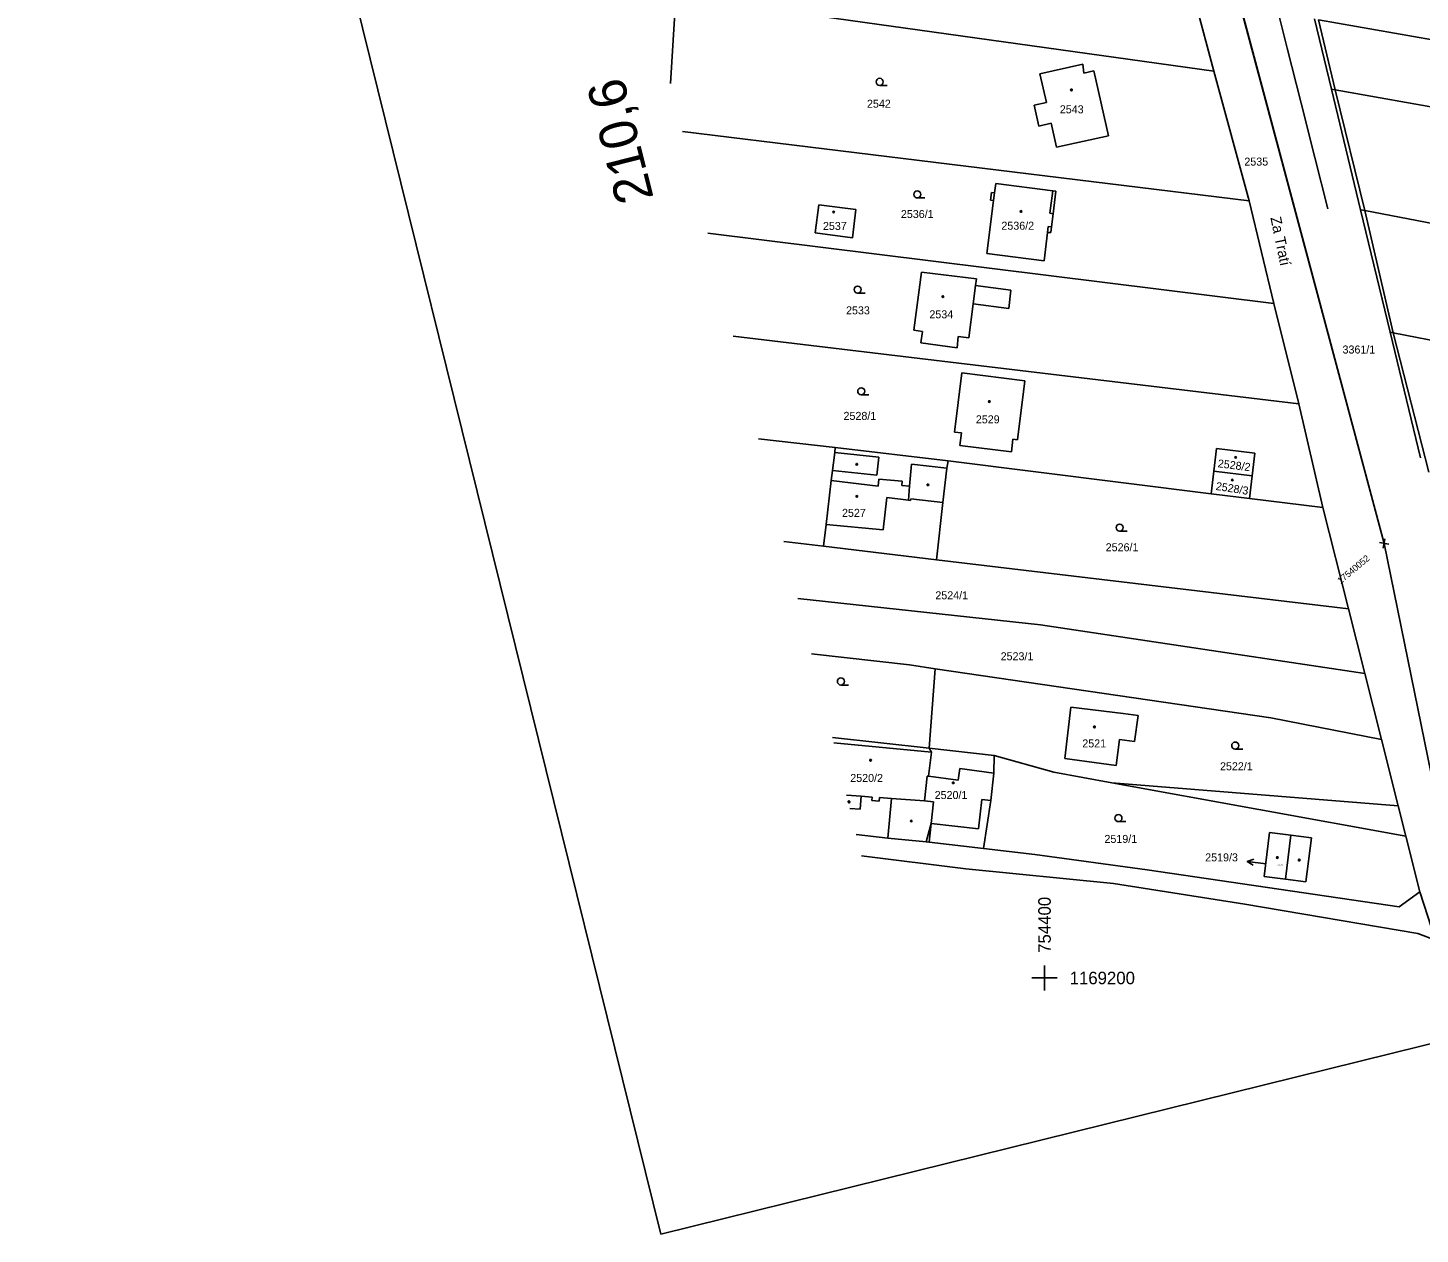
# Model space of a CAD drawing. Extents: x -754679 to -754173, y -1169241 to -1168288.
# Drawn here: x -754562 to -754340.2, y -1169240.8 to -1169048.7 of the extents above; entities that cross this region are included whole.
import ezdxf

# ---------------------------------------------------------------- set-up
doc = ezdxf.new("R2010")
doc.units = 0
for name, color, linetype in [('Default', 7, 'Continuous'), ('Vrstva 1', 7, 'Continuous'), ('Vrstva 13', 7, 'Continuous'), ('Vrstva 15', 7, 'Continuous'), ('Vrstva 16', 7, 'Continuous'), ('Vrstva 18', 7, 'Continuous'), ('Vrstva 19', 7, 'Continuous'), ('Vrstva 25', 7, 'Continuous'), ('Vrstva 4', 7, 'Continuous'), ('Vrstva 52', 7, 'Continuous'), ('Vrstva 53', 7, 'Continuous'), ('Vrstva 60', 7, 'Continuous'), ('Vrstva 61', 7, 'Continuous'), ('Vrstva 7', 7, 'Continuous')]:
    doc.layers.add(name, color=color, linetype=linetype)

msp = doc.modelspace()

# ---------------------------------------------------------------- linework, layer by layer
at = {"layer": 'Default'}
for points in [[(-754400, -1169202), (-754400, -1169200), (-754400, -1169198)], [(-754402, -1169200), (-754400, -1169200), (-754398, -1169200)]]:
    msp.add_lwpolyline(points, dxfattribs=at)
at = {"layer": 'Vrstva 1'}
for p, q in [((-754386.06, -1168980.52), (-754345.91, -1169130.8)), ((-754458.74, -1169043.6), (-754459.56, -1169057.52)), ((-754373.03, -1169055.57), (-754458.74, -1169043.6)), ((-754375.93, -1169044.62), (-754373.03, -1169055.57)), ((-754356.98, -1169047.27), (-754354.28, -1169058.43)), ((-754295.74, -1169058.05), (-754356.33, -1169047.39)), ((-754393.88, -1169054.46), (-754400.75, -1169056)), ((-754393.73, -1169055.89), (-754393.88, -1169054.46)), ((-754400.75, -1169056), (-754399.7, -1169060.55)), ((-754392.13, -1169055.53), (-754393.73, -1169055.89)), ((-754389.81, -1169065.88), (-754392.13, -1169055.53)), ((-754367.41, -1169076.22), (-754373.03, -1169055.57)), ((-754354.28, -1169058.43), (-754353.72, -1169058.53)), ((-754354.28, -1169058.43), (-754349.64, -1169077.64)), ((-754292.92, -1169069.45), (-754353.72, -1169058.53)), ((-754401.67, -1169061), (-754399.7, -1169060.55)), ((-754400.91, -1169064.33), (-754401.67, -1169061)), ((-754398.94, -1169063.88), (-754400.91, -1169064.33)), ((-754398.07, -1169067.71), (-754398.94, -1169063.88)), ((-754457.66, -1169065.21), (-754367.41, -1169076.22)), ((-754389.81, -1169065.88), (-754398.07, -1169067.71)), ((-754408.58, -1169076.1), (-754408.43, -1169074.92)), ((-754408.43, -1169074.92), (-754407.96, -1169074.98)), ((-754407.96, -1169074.98), (-754407.77, -1169073.49)), ((-754407.77, -1169073.49), (-754398.68, -1169074.63)), ((-754398.68, -1169074.63), (-754398.18, -1169074.69)), ((-754398.18, -1169074.69), (-754398.64, -1169078.28)), ((-754436.55, -1169081.34), (-754435.96, -1169076.87)), ((-754435.96, -1169076.87), (-754430.07, -1169077.61)), ((-754409.17, -1169084.63), (-754408.11, -1169076.16)), ((-754408.11, -1169076.16), (-754408.58, -1169076.1)), ((-754367.41, -1169076.22), (-754363.46, -1169092.56)), ((-754430.07, -1169077.61), (-754430.61, -1169082.11)), ((-754398.64, -1169078.28), (-754398.9, -1169080.39)), ((-754348.95, -1169077.77), (-754349.64, -1169077.64)), ((-754349.64, -1169077.64), (-754344.93, -1169097.16)), ((-754287.96, -1169089.49), (-754348.95, -1169077.77)), ((-754453.66, -1169081.38), (-754363.46, -1169092.56)), ((-754430.61, -1169082.11), (-754436.55, -1169081.34)), ((-754399.51, -1169081.26), (-754400.08, -1169085.77)), ((-754399.01, -1169081.3), (-754399.51, -1169081.26)), ((-754398.9, -1169080.39), (-754399.01, -1169081.3)), ((-754400.08, -1169085.77), (-754409.17, -1169084.63)), ((-754420.84, -1169096.85), (-754419.6, -1169087.58)), ((-754419.6, -1169087.58), (-754410.85, -1169088.67)), ((-754410.85, -1169088.67), (-754410.99, -1169089.74)), ((-754410.99, -1169089.74), (-754405.34, -1169090.46)), ((-754405.34, -1169090.46), (-754405.71, -1169093.36)), ((-754411.36, -1169092.64), (-754412.06, -1169098.06)), ((-754405.71, -1169093.36), (-754411.36, -1169092.64)), ((-754363.46, -1169092.56), (-754359.5, -1169108.58)), ((-754419.46, -1169097.03), (-754420.84, -1169096.85)), ((-754419.69, -1169098.86), (-754419.46, -1169097.03)), ((-754344.93, -1169097.16), (-754344.43, -1169097.26)), ((-754344.93, -1169097.16), (-754340.1, -1169117.15)), ((-754344.43, -1169097.26), (-754283.09, -1169109.21)), ((-754359.5, -1169108.58), (-754449.6, -1169097.79)), ((-754413.94, -1169099.63), (-754419.69, -1169098.86)), ((-754413.75, -1169097.84), (-754413.94, -1169099.63)), ((-754412.06, -1169098.06), (-754413.75, -1169097.84)), ((-754414.32, -1169113.06), (-754413.15, -1169103.64)), ((-754413.15, -1169103.64), (-754403.13, -1169104.88)), ((-754403.13, -1169104.88), (-754404.31, -1169114.28)), ((-754359.5, -1169108.58), (-754355.64, -1169125.06)), ((-754433.34, -1169115.54), (-754445.56, -1169114.14)), ((-754413.22, -1169113.2), (-754414.32, -1169113.06)), ((-754413.47, -1169115.21), (-754413.22, -1169113.2)), ((-754405.03, -1169114.19), (-754405.28, -1169116.22)), ((-754404.31, -1169114.28), (-754405.03, -1169114.19)), ((-754433.43, -1169116.33), (-754433.77, -1169119.16)), ((-754433.34, -1169115.54), (-754433.43, -1169116.33)), ((-754415.34, -1169117.65), (-754433.34, -1169115.54)), ((-754405.28, -1169116.22), (-754413.47, -1169115.21)), ((-754373.02, -1169119.29), (-754372.58, -1169115.67)), ((-754372.58, -1169115.67), (-754366.48, -1169116.4)), ((-754366.48, -1169116.4), (-754366.91, -1169120.03)), ((-754433.97, -1169120.78), (-754433.77, -1169119.16)), ((-754416.22, -1169124.26), (-754415.57, -1169118.79)), ((-754415.34, -1169117.65), (-754415.57, -1169118.79)), ((-754373.45, -1169122.92), (-754415.34, -1169117.65)), ((-754373.45, -1169122.92), (-754373.02, -1169119.29)), ((-754366.91, -1169120.03), (-754373.02, -1169119.29)), ((-754434.8, -1169127.79), (-754433.97, -1169120.78)), ((-754366.91, -1169120.03), (-754367.35, -1169123.65)), ((-754367.35, -1169123.65), (-754373.45, -1169122.92)), ((-754355.64, -1169125.06), (-754367.35, -1169123.65)), ((-754417.21, -1169133.39), (-754416.22, -1169124.26)), ((-754351.59, -1169141.22), (-754355.64, -1169125.06)), ((-754435.21, -1169131.25), (-754434.8, -1169127.79)), ((-754441.52, -1169130.5), (-754435.21, -1169131.25)), ((-754417.21, -1169133.39), (-754435.21, -1169131.25)), ((-754345.91, -1169130.8), (-754333.91, -1169189.61)), ((-754351.59, -1169141.22), (-754417.21, -1169133.39)), ((-754439.28, -1169139.55), (-754400.66, -1169143.78)), ((-754351.59, -1169141.22), (-754348.98, -1169151.49)), ((-754348.98, -1169151.49), (-754400.66, -1169143.78)), ((-754421.5, -1169150.11), (-754437.1, -1169148.37)), ((-754417.44, -1169150.77), (-754421.5, -1169150.11)), ((-754417.44, -1169150.77), (-754418.36, -1169163.42)), ((-754363.94, -1169158.55), (-754417.44, -1169150.77)), ((-754348.98, -1169151.49), (-754346.3, -1169162)), ((-754395.79, -1169156.85), (-754396.77, -1169165.07)), ((-754387.47, -1169157.88), (-754395.79, -1169156.85)), ((-754385.1, -1169158.21), (-754387.47, -1169157.88)), ((-754385.67, -1169162.35), (-754385.1, -1169158.21)), ((-754346.3, -1169162), (-754363.94, -1169158.55)), ((-754418.36, -1169163.42), (-754433.8, -1169161.68)), ((-754418.36, -1169163.42), (-754408.03, -1169164.58)), ((-754418.36, -1169163.42), (-754418.03, -1169164.01)), ((-754388.61, -1169166.17), (-754388.04, -1169162.02)), ((-754388.04, -1169162.02), (-754385.67, -1169162.35)), ((-754343.65, -1169172.58), (-754346.3, -1169162)), ((-754418.03, -1169164.01), (-754418.47, -1169167.87)), ((-754408.03, -1169164.58), (-754408.08, -1169167.38)), ((-754398.5, -1169167.22), (-754408.03, -1169164.58)), ((-754396.77, -1169165.07), (-754388.61, -1169166.17)), ((-754419.12, -1169171.81), (-754418.67, -1169167.85)), ((-754418.47, -1169167.87), (-754418.67, -1169167.85)), ((-754408.08, -1169167.38), (-754408.55, -1169171.72)), ((-754389.3, -1169168.9), (-754398.5, -1169167.22)), ((-754342.43, -1169177.43), (-754389.3, -1169168.9)), ((-754417.68, -1169171.97), (-754419.12, -1169171.81)), ((-754418.05, -1169175.38), (-754417.68, -1169171.97)), ((-754408.55, -1169171.72), (-754409.73, -1169179.38)), ((-754342.43, -1169177.43), (-754343.65, -1169172.58)), ((-754429.98, -1169177.14), (-754424.97, -1169177.74)), ((-754418.05, -1169175.38), (-754418.84, -1169178.34)), ((-754365.03, -1169183.83), (-754364.13, -1169176.81)), ((-754364.13, -1169176.81), (-754360.78, -1169177.24)), ((-754360.78, -1169177.24), (-754357.48, -1169177.66)), ((-754424.97, -1169177.74), (-754418.84, -1169178.34)), ((-754418.84, -1169178.34), (-754418.38, -1169178.38)), ((-754418.38, -1169178.38), (-754409.73, -1169179.38)), ((-754409.73, -1169179.38), (-754401.54, -1169180.32)), ((-754357.48, -1169177.66), (-754358.38, -1169184.68)), ((-754340.21, -1169186.28), (-754342.43, -1169177.43)), ((-754401.54, -1169180.32), (-754383.66, -1169182.78)), ((-754383.66, -1169182.78), (-754343.51, -1169188.69)), ((-754361.6, -1169184.27), (-754365.03, -1169183.83)), ((-754358.38, -1169184.68), (-754361.6, -1169184.27)), ((-754343.51, -1169188.69), (-754340.21, -1169186.28)), ((-754340.21, -1169186.28), (-754337.71, -1169193.96))]:
    msp.add_line(p, q, dxfattribs=at)
msp.add_lwpolyline([(-754354.86, -1169077.5), (-754356.93, -1169069.33), (-754359.12, -1169060.65), (-754361.33, -1169051.91), (-754363.43, -1169043.59), (-754365, -1169037.37), (-754367.34, -1169028.11), (-754369.54, -1169019.37), (-754371.76, -1169010.62)], dxfattribs=at)
at = {"layer": 'Vrstva 13'}
for p, q in [((-754429.14, -1169180.52), (-754412.56, -1169182.61)), ((-754412.56, -1169182.61), (-754389.02, -1169184.95)), ((-754389.02, -1169184.95), (-754368.1, -1169188.22)), ((-754368.1, -1169188.22), (-754340.53, -1169192.94)), ((-754340.53, -1169192.94), (-754337.71, -1169193.96))]:
    msp.add_line(p, q, dxfattribs=at)
at = {"layer": 'Vrstva 16'}
msp.add_line((-754367.69, -1169181.43), (-754364.71, -1169181.81), dxfattribs=at)
msp.add_lwpolyline([(-754366.76, -1169182.05), (-754367.69, -1169181.43), (-754366.63, -1169181.06)], dxfattribs=at)
at = {"layer": 'Vrstva 25'}
for p, q in [((-754426.26, -1169057.84), (-754425.06, -1169057.84)), ((-754420.27, -1169075.77), (-754419.07, -1169075.77)), ((-754429.77, -1169090.93), (-754428.57, -1169090.93)), ((-754429.2, -1169107.12), (-754428, -1169107.12)), ((-754388.03, -1169128.83), (-754386.83, -1169128.83)), ((-754432.44, -1169153.34), (-754431.24, -1169153.34)), ((-754369.62, -1169163.54), (-754368.42, -1169163.54)), ((-754431.3, -1169171.82), (-754431.22, -1169172.13)), ((-754388.22, -1169175.1), (-754387.02, -1169175.1))]:
    msp.add_line(p, q, dxfattribs=at)
for centre, radius in [((-754426.26, -1169057.28), 0.562), ((-754395.71, -1169058.56), 0.131), ((-754420.27, -1169075.21), 0.562), ((-754433.58, -1169078.01), 0.131), ((-754403.75, -1169077.92), 0.131), ((-754429.77, -1169090.37), 0.562), ((-754416.19, -1169091.48), 0.131), ((-754429.2, -1169106.56), 0.562), ((-754408.79, -1169108.2), 0.131), ((-754369.54, -1169117.08), 0.131), ((-754429.91, -1169118.19), 0.131), ((-754418.58, -1169121.46), 0.131), ((-754370.09, -1169120.69), 0.131), ((-754429.89, -1169123.3), 0.131), ((-754388.03, -1169128.27), 0.562), ((-754432.44, -1169152.78), 0.562), ((-754392.04, -1169160.01), 0.131), ((-754369.62, -1169162.98), 0.562), ((-754427.71, -1169165.32), 0.131), ((-754414.55, -1169168.92), 0.131), ((-754421.23, -1169174.99), 0.131), ((-754388.22, -1169174.54), 0.562), ((-754362.9, -1169180.82), 0.131), ((-754359.42, -1169181.23), 0.131)]:
    msp.add_circle(centre, radius, dxfattribs=at)
msp.add_arc((-754431.19, -1169171.96), 0.175, 260.291, 127.4882, dxfattribs=at)
at = {"layer": 'Vrstva 4'}
for p, q in [((-754353.72, -1169058.53), (-754356.33, -1169047.39)), ((-754348.95, -1169077.77), (-754353.72, -1169058.53)), ((-754408.11, -1169076.16), (-754407.96, -1169074.98)), ((-754399.13, -1169078.22), (-754398.68, -1169074.63)), ((-754398.64, -1169078.28), (-754399.13, -1169078.22)), ((-754344.43, -1169097.26), (-754348.95, -1169077.77)), ((-754399.51, -1169081.26), (-754399.4, -1169080.33)), ((-754399.4, -1169080.33), (-754398.9, -1169080.39)), ((-754410.99, -1169089.74), (-754411.36, -1169092.64)), ((-754338.76, -1169119.45), (-754344.43, -1169097.26)), ((-754433.43, -1169116.33), (-754426.37, -1169117.08)), ((-754426.37, -1169117.08), (-754426.71, -1169119.93)), ((-754426.71, -1169119.93), (-754433.77, -1169119.16)), ((-754421.21, -1169118.16), (-754421.49, -1169121.69)), ((-754415.57, -1169118.79), (-754421.21, -1169118.16)), ((-754426.5, -1169121.67), (-754433.97, -1169120.78)), ((-754426.37, -1169120.58), (-754426.5, -1169121.67)), ((-754422.67, -1169120.89), (-754426.37, -1169120.58)), ((-754422.73, -1169121.59), (-754422.67, -1169120.89)), ((-754421.49, -1169121.69), (-754422.73, -1169121.59)), ((-754421.67, -1169123.91), (-754421.49, -1169121.69)), ((-754425.71, -1169128.61), (-754425.1, -1169123.5)), ((-754425.1, -1169123.5), (-754421.67, -1169123.91)), ((-754421.33, -1169123.94), (-754421.67, -1169123.91)), ((-754421.3, -1169123.7), (-754421.33, -1169123.94)), ((-754416.22, -1169124.26), (-754421.3, -1169123.7)), ((-754434.8, -1169127.79), (-754425.71, -1169128.61)), ((-754433.58, -1169162.57), (-754418.03, -1169164.01)), ((-754418.47, -1169167.87), (-754413.73, -1169168.5)), ((-754413.48, -1169166.66), (-754413.73, -1169168.5)), ((-754413.48, -1169166.66), (-754408.08, -1169167.38)), ((-754389.3, -1169168.9), (-754343.65, -1169172.58)), ((-754431.53, -1169170.88), (-754429.23, -1169171.05)), ((-754429.23, -1169171.05), (-754429.38, -1169173.13)), ((-754427.45, -1169171.19), (-754429.23, -1169171.05)), ((-754427.5, -1169171.76), (-754427.45, -1169171.19)), ((-754426.35, -1169171.85), (-754427.5, -1169171.76)), ((-754426.3, -1169171.27), (-754426.35, -1169171.85)), ((-754424.36, -1169171.42), (-754426.3, -1169171.27)), ((-754424.36, -1169171.42), (-754424.97, -1169177.74)), ((-754419.12, -1169171.81), (-754424.36, -1169171.42)), ((-754409.99, -1169171.57), (-754410.49, -1169176.22)), ((-754408.55, -1169171.72), (-754409.99, -1169171.57)), ((-754429.38, -1169173.13), (-754431.01, -1169172.99)), ((-754418.05, -1169175.38), (-754418.38, -1169178.38)), ((-754418.05, -1169175.38), (-754410.49, -1169176.22)), ((-754360.78, -1169177.24), (-754361.6, -1169184.27))]:
    msp.add_line(p, q, dxfattribs=at)
at = {"layer": 'Vrstva 53'}
msp.add_lwpolyline([(-754345.91, -1169130.8), (-754386.06, -1168980.52), (-754394.57, -1168948.26)], dxfattribs=at)
at = {"layer": 'Vrstva 60'}
for p, q in [((-754345.78, -1169130.06), (-754346.04, -1169131.54)), ((-754346.65, -1169130.67), (-754345.17, -1169130.93))]:
    msp.add_line(p, q, dxfattribs=at)
at = {"layer": 'Vrstva 61'}
msp.add_line((-754561.97, -1168833.08), (-754461.15, -1169240.8), dxfattribs=at)
msp.add_lwpolyline([(-754461.15, -1169240.8), (-754172.83, -1169169.5), (-754273.65, -1168761.78), (-754561.97, -1168833.08)], dxfattribs=at)

# ---------------------------------------------------------------- texts
at = {"layer": 'Default'}
msp.add_text('754400', height=2, rotation=90, dxfattribs=at).set_placement((-754399, -1169196))
msp.add_text('1169200', height=2, dxfattribs=at).set_placement((-754396, -1169201))
at = {"layer": 'Vrstva 15'}
msp.add_text('Za Tratí', height=1.7, rotation=281.7233, dxfattribs=at).set_placement((-754364.02, -1169078.92))
at = {"layer": 'Vrstva 16'}
msp.add_text('2519/3', height=1.275, rotation=360, dxfattribs=at).set_placement((-754374.4, -1169181.43))
at = {"layer": 'Vrstva 18'}
for s, p in [('2542', (-754428.28, -1169061.4)), ('2535', (-754368.16, -1169070.62)), ('2536/1', (-754422.88, -1169078.97)), ('2533', (-754431.62, -1169094.31)), ('3361/1', (-754352.52, -1169100.55)), ('2528/1', (-754432.02, -1169111.12)), ('2526/1', (-754390.25, -1169132.04)), ('2524/1', (-754417.39, -1169139.69)), ('2523/1', (-754406.99, -1169149.4)), ('2522/1', (-754372.04, -1169166.92)), ('2519/1', (-754390.45, -1169178.49))]:
    msp.add_text(s, height=1.275, rotation=360, dxfattribs=at).set_placement(p)
at = {"layer": 'Vrstva 19'}
for s, rotation, p in [('2543', 360, (-754397.56, -1169062.29)), ('2537', 360, (-754435.3, -1169080.87)), ('2536/2', 360, (-754406.87, -1169080.83)), ('2534', 360, (-754418.34, -1169094.94)), ('2529', 360, (-754410.94, -1169111.67)), ('2528/2', 352.8847, (-754372.45, -1169118.65)), ('2528/3', 351.2231, (-754372.78, -1169122.26)), ('2527', 360, (-754432.26, -1169126.56)), ('2521', 360, (-754393.98, -1169163.28)), ('2520/2', 360, (-754430.95, -1169168.78)), ('2520/1', 360, (-754417.5, -1169171.5))]:
    msp.add_text(s, height=1.275, rotation=rotation, dxfattribs=at).set_placement(p)
msp.add_text('2519/3', height=0.2, dxfattribs=at).set_placement((-754362.87, -1169182.04))
at = {"layer": 'Vrstva 52'}
msp.add_text(' 17540052', height=1.037, rotation=40, dxfattribs=at).set_placement((-754353.12, -1169137.55))
at = {"layer": 'Vrstva 7'}
msp.add_text('210,6', height=6, rotation=104.1853, dxfattribs=at).set_placement((-754462.24, -1169075.76))

doc.saveas('drawing.dxf')
